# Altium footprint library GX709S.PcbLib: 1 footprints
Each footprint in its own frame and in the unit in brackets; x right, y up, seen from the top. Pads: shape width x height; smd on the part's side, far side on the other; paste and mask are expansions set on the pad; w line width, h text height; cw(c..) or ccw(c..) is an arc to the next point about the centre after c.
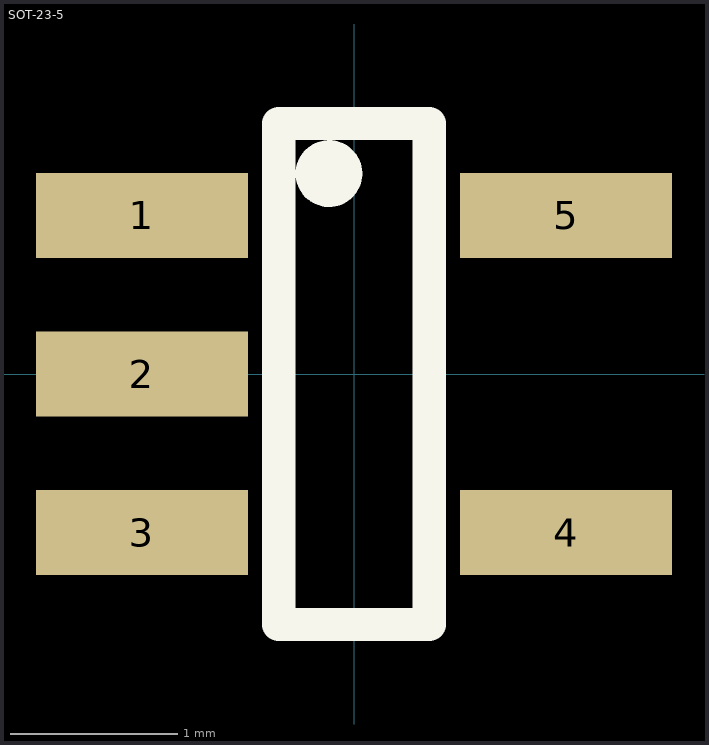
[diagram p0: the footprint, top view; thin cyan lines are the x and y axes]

## SOT-23-5 [mil]
pads (5):
  rect 50x20 smd mask+0.98: 1(-50,37.4) 2(-50,0) 3(-50,-37.4) 4(50,-37.4) 5(50,37.4)
Top Overlay:
  circle w7.87: c-5.91,47.24 r3.94
  lines w7.87: -17.72,-59.06 -17.72,59.06 17.72,59.06 17.72,-59.06 -17.72,-59.06
3D body "User Library-SOT23-5.STEP": height 42.79, standoff -0.51, extent -57.91,-57.06 52.34,57.09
